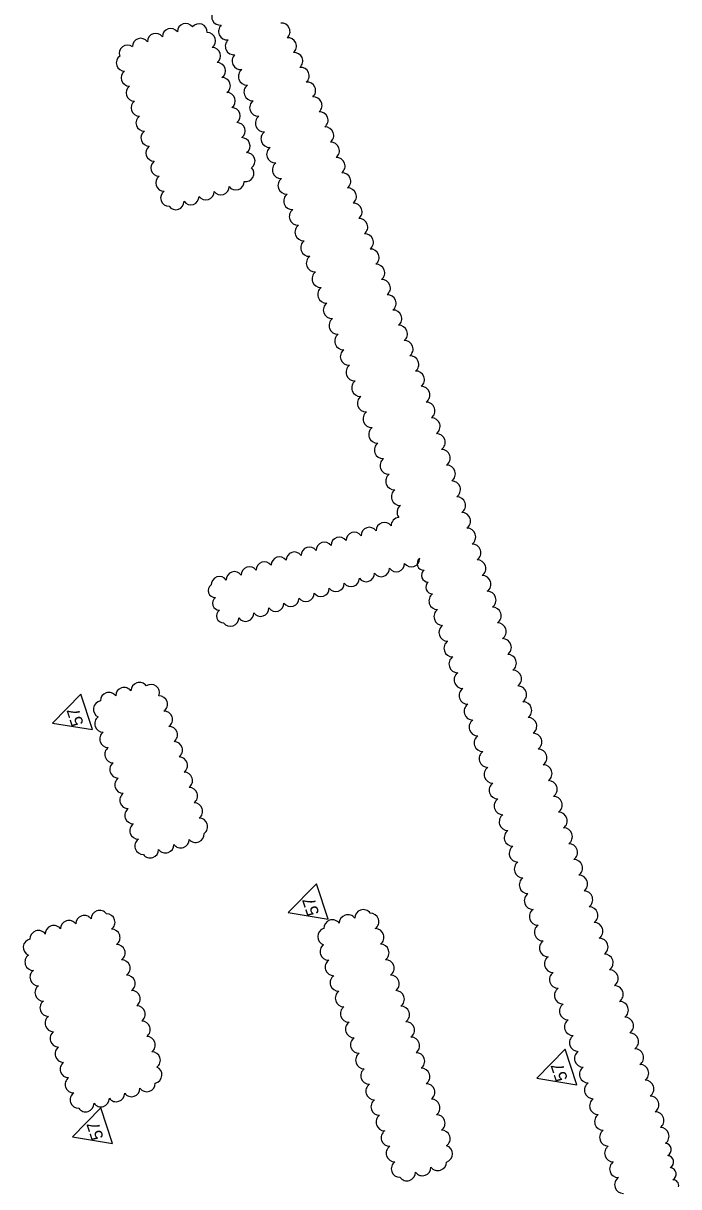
# Model space of a CAD drawing. Extents: x 929207 to 930387, y 631822 to 633132.
# Drawn here: x 929482 to 929778, y 632087 to 632613 of the extents above; entities that cross this region are included whole.
import ezdxf

# ---------------------------------------------------------------- set-up
doc = ezdxf.new("R2010")
doc.units = 0
doc.layers.add('PoleLight', color=7, linetype='Continuous')

msp = doc.modelspace()

# ---------------------------------------------------------------- linework, layer by layer
at = {"layer": 'PoleLight'}
for points in [[(929494.95, 632296.63), (929513.05, 632293.68), (929507.78, 632309.74)], [(929601.64, 632210.81), (929619.74, 632207.86), (929614.46, 632223.92)], [(929714.17, 632135.84), (929732.27, 632132.89), (929726.99, 632148.95)], [(929503.96, 632109.27), (929522.06, 632106.32), (929516.78, 632122.38)]]:
    msp.add_lwpolyline(points, close=True, dxfattribs=at)
for centre, radius, start, end in [((929570.83, 632616.45), 3.87, 132.1575, 277.1575), ((929541.6, 632605.1), 3.75, 35.6866, 180.6866), ((929548.4, 632607.33), 3.75, 35.6866, 180.6866), ((929555.19, 632609.56), 3.75, 35.6866, 180.6866), ((929561.18, 632609.43), 3.75, 356.7237, 141.7237), ((929564.97, 632605.47), 3.75, 305.6866, 90.6866), ((929573.92, 632609.74), 3.87, 132.1575, 277.1575), ((929598.62, 632609.71), 3.82, 310.9237, 95.9237), ((929528.86, 632599.78), 3.75, 54.2081, 199.2081), ((929534.8, 632602.87), 3.75, 35.6866, 180.6866), ((929577, 632603.02), 3.87, 132.1575, 277.1575), ((929601.52, 632603.02), 3.82, 310.9237, 95.9237), ((929527.51, 632595.5), 3.75, 125.6866, 270.6866), ((929567.2, 632598.67), 3.75, 305.6866, 90.6866), ((929580.08, 632596.31), 3.87, 132.1575, 277.1575), ((929604.41, 632596.33), 3.82, 310.9237, 95.9237), ((929569.44, 632591.87), 3.75, 305.6866, 90.6866), ((929607.31, 632589.64), 3.82, 310.9237, 95.9237), ((929529.74, 632588.71), 3.75, 125.6866, 270.6866), ((929571.67, 632585.08), 3.75, 305.6866, 90.6866), ((929582.96, 632589.35), 3.93, 127.5144, 272.5144), ((929531.98, 632581.91), 3.75, 125.6866, 270.6866), ((929585.52, 632582.3), 3.93, 127.5144, 272.5144), ((929610.21, 632582.95), 3.82, 310.9237, 95.9237), ((929534.21, 632575.11), 3.75, 125.6866, 270.6866), ((929573.9, 632578.28), 3.75, 305.6866, 90.6866), ((929588.09, 632575.26), 3.93, 127.5144, 272.5144), ((929613.11, 632576.26), 3.82, 310.9237, 95.9237), ((929576.13, 632571.48), 3.75, 305.6866, 90.6866), ((929615.81, 632569.51), 3.86, 307.897, 92.897), ((929536.44, 632568.32), 3.75, 125.6866, 270.6866), ((929578.37, 632564.69), 3.75, 305.6866, 90.6866), ((929590.66, 632568.21), 3.93, 127.5144, 272.5144), ((929618.38, 632562.61), 3.86, 307.897, 92.897), ((929538.67, 632561.52), 3.75, 125.6866, 270.6866), ((929580.6, 632557.89), 3.75, 305.6866, 90.6866), ((929593.22, 632561.16), 3.93, 127.5144, 272.5144), ((929540.91, 632554.72), 3.75, 125.6866, 270.6866), ((929595.79, 632554.12), 3.93, 127.5144, 272.5144), ((929620.95, 632555.7), 3.86, 307.897, 92.897), ((929543.14, 632547.93), 3.75, 125.6866, 270.6866), ((929582.83, 632551.09), 3.75, 305.6866, 90.6866), ((929623.51, 632548.8), 3.86, 307.897, 92.897), ((929582.33, 632545.43), 3.75, 259.2222, 44.2222), ((929598.36, 632547.07), 3.93, 127.5144, 272.5144), ((929626.08, 632541.89), 3.86, 307.897, 92.897), ((929545.37, 632541.13), 3.75, 125.6866, 270.6866), ((929577.88, 632541.7), 3.75, 215.6866, 0.6866), ((929600.92, 632540.03), 3.93, 127.5144, 272.5144), ((929547.61, 632534.33), 3.75, 125.6866, 270.6866), ((929557.49, 632535.01), 3.75, 215.6866, 0.6866), ((929564.29, 632537.24), 3.75, 215.6866, 0.6866), ((929571.09, 632539.47), 3.75, 215.6866, 0.6866), ((929603.49, 632532.98), 3.93, 127.5144, 272.5144), ((929628.65, 632534.99), 3.86, 307.897, 92.897), ((929550.7, 632532.77), 3.75, 215.6866, 0.6866), ((929631.22, 632528.08), 3.86, 307.897, 92.897), ((929606.05, 632525.94), 3.93, 127.5144, 272.5144), ((929633.78, 632521.18), 3.86, 307.897, 92.897), ((929608.62, 632518.89), 3.93, 127.5144, 272.5144), ((929611.19, 632511.84), 3.93, 127.5144, 272.5144), ((929636.35, 632514.27), 3.86, 307.897, 92.897), ((929638.92, 632507.37), 3.86, 307.897, 92.897), ((929613.75, 632504.8), 3.93, 127.5144, 272.5144), ((929641.49, 632500.46), 3.86, 307.897, 92.897), ((929616.32, 632497.75), 3.93, 127.5144, 272.5144), ((929618.89, 632490.71), 3.93, 127.5144, 272.5144), ((929644.05, 632493.56), 3.86, 307.897, 92.897), ((929646.62, 632486.65), 3.86, 307.897, 92.897), ((929621.45, 632483.66), 3.93, 127.5144, 272.5144), ((929649.19, 632479.75), 3.86, 307.897, 92.897), ((929624.02, 632476.61), 3.93, 127.5144, 272.5144), ((929626.59, 632469.57), 3.93, 127.5144, 272.5144), ((929651.76, 632472.84), 3.86, 307.897, 92.897), ((929654.32, 632465.94), 3.86, 307.897, 92.897), ((929629.15, 632462.52), 3.93, 127.5144, 272.5144), ((929656.89, 632459.03), 3.86, 307.897, 92.897), ((929631.72, 632455.48), 3.93, 127.5144, 272.5144), ((929659.46, 632452.13), 3.86, 307.897, 92.897), ((929634.29, 632448.43), 3.93, 127.5144, 272.5144), ((929661.86, 632445.14), 3.93, 305.3886, 90.3886), ((929636.85, 632441.39), 3.93, 127.5144, 272.5144), ((929664.16, 632438.01), 3.93, 305.3886, 90.3886), ((929639.42, 632434.34), 3.93, 127.5144, 272.5144), ((929666.47, 632430.87), 3.93, 305.3886, 90.3886), ((929641.99, 632427.29), 3.93, 127.5144, 272.5144), ((929668.77, 632423.73), 3.93, 305.3886, 90.3886), ((929644.55, 632420.25), 3.93, 127.5144, 272.5144), ((929671.08, 632416.59), 3.93, 305.3886, 90.3886), ((929647.12, 632413.2), 3.93, 127.5144, 272.5144), ((929649.68, 632406.16), 3.93, 127.5144, 272.5144), ((929673.38, 632409.45), 3.93, 305.3886, 90.3886), ((929675.68, 632402.31), 3.93, 305.3886, 90.3886), ((929652.25, 632399.11), 3.93, 127.5144, 272.5144), ((929677.99, 632395.17), 3.93, 305.3886, 90.3886), ((929654.82, 632392.07), 3.93, 127.5144, 217.1821), ((929645.16, 632383.72), 3.75, 35.6866, 180.6866), ((929651.95, 632385.95), 3.75, 94.0099, 180.6866), ((929680.29, 632388.03), 3.93, 305.3886, 90.3886), ((929631.58, 632379.26), 3.75, 35.6866, 180.6866), ((929638.37, 632381.49), 3.75, 35.6866, 180.6866), ((929682.6, 632380.89), 3.93, 305.3886, 90.3886), ((929618.01, 632374.8), 3.75, 35.6866, 180.6866), ((929624.79, 632377.03), 3.75, 35.6866, 180.6866), ((929684.9, 632373.75), 3.93, 305.3886, 90.3886), ((929597.64, 632368.11), 3.75, 35.6866, 180.6866), ((929604.43, 632370.34), 3.75, 35.6866, 180.6866), ((929611.22, 632372.57), 3.75, 35.6866, 180.6866), ((929584.06, 632363.65), 3.75, 35.6866, 180.6866), ((929590.85, 632365.88), 3.75, 35.6866, 180.6866), ((929643.74, 632366.64), 3.77, 215.6866, 0.6866), ((929650.57, 632368.88), 3.77, 215.6866, 0.6866), ((929657.4, 632371.12), 3.77, 215.6866, 0.6866), ((929662.99, 632368.8), 2.98, 127.5144, 272.5144), ((929687.21, 632366.61), 3.93, 305.3886, 90.3886), ((929570.49, 632359.19), 3.75, 35.6866, 180.6866), ((929577.27, 632361.42), 3.75, 35.6866, 180.6866), ((929630.08, 632362.15), 3.77, 215.6866, 0.6866), ((929636.91, 632364.39), 3.77, 215.6866, 0.6866), ((929664.93, 632363.46), 2.98, 127.5144, 272.5144), ((929689.51, 632359.47), 3.93, 305.3886, 90.3886), ((929568.58, 632356.58), 3.15, 125.6866, 270.6866), ((929616.42, 632357.66), 3.77, 215.6866, 0.6866), ((929623.25, 632359.9), 3.77, 215.6866, 0.6866), ((929666.88, 632358.12), 2.98, 127.5144, 272.5144), ((929691.81, 632352.33), 3.93, 305.3886, 90.3886), ((929570.46, 632350.87), 3.15, 125.6866, 270.6866), ((929595.93, 632350.93), 3.77, 215.6866, 0.6866), ((929602.76, 632353.17), 3.77, 215.6866, 0.6866), ((929609.59, 632355.42), 3.77, 215.6866, 0.6866), ((929669.27, 632351.93), 3.93, 125.154, 270.154), ((929572.34, 632345.15), 3.15, 125.6866, 270.6866), ((929582.27, 632346.44), 3.77, 215.6866, 0.6866), ((929589.1, 632348.68), 3.77, 215.6866, 0.6866), ((929671.54, 632344.79), 3.93, 125.154, 270.154), ((929694.12, 632345.19), 3.93, 305.3886, 90.3886), ((929575.44, 632344.2), 3.77, 215.6866, 0.6866), ((929673.82, 632337.65), 3.93, 125.154, 270.154), ((929696.42, 632338.05), 3.93, 305.3886, 90.3886), ((929698.73, 632330.91), 3.93, 305.3886, 90.3886), ((929676.09, 632330.5), 3.93, 125.154, 270.154), ((929678.36, 632323.36), 3.93, 125.154, 270.154), ((929701.03, 632323.77), 3.93, 305.3886, 90.3886), ((929680.64, 632316.22), 3.93, 125.154, 270.154), ((929703.34, 632316.64), 3.93, 305.3886, 90.3886), ((929534.23, 632311.21), 3.82, 35.6866, 180.6866), ((929539.5, 632310.29), 3.82, 339.6034, 124.6034), ((929520.4, 632306.67), 3.82, 35.6866, 180.6866), ((929527.32, 632308.94), 3.82, 35.6866, 180.6866), ((929543.13, 632305.14), 3.82, 305.6866, 90.6866), ((929682.91, 632309.07), 3.93, 125.154, 270.154), ((929705.64, 632309.5), 3.93, 305.3886, 90.3886), ((929517.21, 632302.86), 3.81, 99.5768, 244.5768), ((929685.18, 632301.93), 3.93, 125.154, 270.154), ((929707.95, 632302.36), 3.93, 305.3886, 90.3886), ((929517.8, 632296.31), 3.82, 125.6866, 270.6866), ((929545.4, 632298.23), 3.82, 305.6866, 90.6866), ((929687.46, 632294.79), 3.93, 125.154, 270.154), ((929710.25, 632295.22), 3.93, 305.3886, 90.3886), ((929520.08, 632289.39), 3.82, 125.6866, 270.6866), ((929547.67, 632291.31), 3.82, 305.6866, 90.6866), ((929549.95, 632284.39), 3.82, 305.6866, 90.6866), ((929689.73, 632287.64), 3.93, 125.154, 270.154), ((929712.55, 632288.08), 3.93, 305.3886, 90.3886), ((929522.35, 632282.48), 3.82, 125.6866, 270.6866), ((929692, 632280.5), 3.93, 125.154, 270.154), ((929714.86, 632280.94), 3.93, 305.3886, 90.3886), ((929524.62, 632275.56), 3.82, 125.6866, 270.6866), ((929552.22, 632277.47), 3.82, 305.6866, 90.6866), ((929717.16, 632273.8), 3.93, 305.3886, 90.3886), ((929526.89, 632268.64), 3.82, 125.6866, 270.6866), ((929554.49, 632270.55), 3.82, 305.6866, 90.6866), ((929694.28, 632273.36), 3.93, 125.154, 270.154), ((929556.76, 632263.64), 3.82, 305.6866, 90.6866), ((929696.55, 632266.21), 3.93, 125.154, 270.154), ((929719.47, 632266.66), 3.93, 305.3886, 90.3886), ((929529.17, 632261.72), 3.82, 125.6866, 270.6866), ((929698.82, 632259.07), 3.93, 125.154, 270.154), ((929721.77, 632259.52), 3.93, 305.3886, 90.3886), ((929531.44, 632254.8), 3.82, 125.6866, 270.6866), ((929559.04, 632256.72), 3.82, 305.6866, 90.6866), ((929724.08, 632252.38), 3.93, 305.3886, 90.3886), ((929533.71, 632247.89), 3.82, 125.6866, 270.6866), ((929561.31, 632249.8), 3.82, 305.6866, 90.6866), ((929701.1, 632251.93), 3.93, 125.154, 270.154), ((929559.73, 632246.4), 3.82, 219.4956, 4.4956), ((929703.37, 632244.79), 3.93, 125.154, 270.154), ((929726.38, 632245.24), 3.93, 305.3886, 90.3886), ((929535.99, 632240.97), 3.82, 125.6866, 270.6866), ((929546.05, 632241.65), 3.82, 215.6866, 0.6866), ((929552.97, 632243.92), 3.82, 215.6866, 0.6866), ((929705.64, 632237.64), 3.93, 125.154, 270.154), ((929728.69, 632238.1), 3.93, 305.3886, 90.3886), ((929539.13, 632239.38), 3.82, 215.6866, 0.6866), ((929730.99, 632230.96), 3.93, 305.3886, 90.3886), ((929707.92, 632230.5), 3.93, 125.154, 270.154), ((929710.19, 632223.36), 3.93, 125.154, 270.154), ((929733.29, 632223.82), 3.93, 305.3886, 90.3886), ((929712.46, 632216.21), 3.93, 125.154, 270.154), ((929735.6, 632216.68), 3.93, 305.3886, 90.3886), ((929737.9, 632209.54), 3.93, 305.3886, 90.3886), ((929509.29, 632205.73), 3.83, 35.6866, 180.6866), ((929516.22, 632208.01), 3.83, 35.6866, 180.6866), ((929519.38, 632206.42), 3.83, 305.6866, 90.6866), ((929628.6, 632206.02), 3.87, 35.6866, 180.6866), ((929635.62, 632208.32), 3.87, 35.6866, 180.6866), ((929638.81, 632206.71), 3.87, 305.6866, 90.6866), ((929714.74, 632209.07), 3.93, 125.154, 270.154), ((929495.42, 632201.17), 3.83, 35.6866, 180.6866), ((929502.35, 632203.45), 3.83, 35.6866, 180.6866), ((929521.66, 632199.48), 3.83, 305.6866, 90.6866), ((929618.84, 632199.96), 3.87, 106.858, 251.858), ((929621.59, 632203.71), 3.87, 35.6866, 180.6866), ((929641.12, 632199.69), 3.87, 305.6866, 90.6866), ((929717.01, 632201.93), 3.93, 125.154, 270.154), ((929740.21, 632202.4), 3.93, 305.3886, 90.3886), ((929485.46, 632195.11), 3.82, 102.1164, 247.1164), ((929488.48, 632198.9), 3.83, 35.6866, 180.6866), ((929719.28, 632194.78), 3.93, 125.154, 270.154), ((929742.51, 632195.27), 3.93, 305.3886, 90.3886), ((929523.93, 632192.55), 3.83, 305.6866, 90.6866), ((929619.89, 632193.13), 3.87, 125.6866, 270.6866), ((929643.43, 632192.67), 3.87, 305.6866, 90.6866), ((929486.21, 632188.48), 3.83, 125.6866, 270.6866), ((929526.21, 632185.61), 3.83, 305.6866, 90.6866), ((929622.2, 632186.12), 3.87, 125.6866, 270.6866), ((929645.73, 632185.65), 3.87, 305.6866, 90.6866), ((929721.56, 632187.64), 3.93, 125.154, 270.154), ((929744.82, 632188.13), 3.93, 305.3886, 90.3886), ((929488.48, 632181.55), 3.83, 125.6866, 270.6866), ((929528.49, 632178.68), 3.83, 305.6866, 90.6866), ((929624.5, 632179.1), 3.87, 125.6866, 270.6866), ((929648.04, 632178.64), 3.87, 305.6866, 90.6866), ((929723.83, 632180.5), 3.93, 125.154, 270.154), ((929747.12, 632180.99), 3.93, 305.3886, 90.3886), ((929490.76, 632174.61), 3.83, 125.6866, 270.6866), ((929726.1, 632173.35), 3.93, 125.154, 270.154), ((929749.42, 632173.85), 3.93, 305.3886, 90.3886), ((929530.77, 632171.74), 3.83, 305.6866, 90.6866), ((929626.81, 632172.08), 3.87, 125.6866, 270.6866), ((929650.34, 632171.62), 3.87, 305.6866, 90.6866), ((929493.04, 632167.68), 3.83, 125.6866, 270.6866), ((929533.05, 632164.81), 3.83, 305.6866, 90.6866), ((929629.11, 632165.06), 3.87, 125.6866, 270.6866), ((929652.65, 632164.6), 3.87, 305.6866, 90.6866), ((929728.38, 632166.21), 3.93, 125.154, 270.154), ((929751.73, 632166.71), 3.93, 305.3886, 90.3886), ((929495.32, 632160.74), 3.83, 125.6866, 270.6866), ((929535.32, 632157.87), 3.83, 305.6866, 90.6866), ((929631.42, 632158.04), 3.87, 125.6866, 270.6866), ((929654.95, 632157.58), 3.87, 305.6866, 90.6866), ((929730.65, 632159.07), 3.93, 125.154, 270.154), ((929754.03, 632159.57), 3.93, 305.3886, 90.3886), ((929497.6, 632153.81), 3.83, 125.6866, 270.6866), ((929756.34, 632152.43), 3.93, 305.3886, 90.3886), ((929537.6, 632150.94), 3.83, 305.6866, 90.6866), ((929633.72, 632151.02), 3.87, 125.6866, 270.6866), ((929657.26, 632150.56), 3.87, 305.6866, 90.6866), ((929732.92, 632151.92), 3.93, 125.154, 270.154), ((929499.87, 632146.87), 3.83, 125.6866, 270.6866), ((929539.88, 632144), 3.83, 305.6866, 90.6866), ((929636.03, 632144.01), 3.87, 125.6866, 270.6866), ((929659.57, 632143.54), 3.87, 305.6866, 90.6866), ((929735.2, 632144.78), 3.93, 125.154, 270.154), ((929758.64, 632145.29), 3.93, 305.3886, 90.3886), ((929502.15, 632139.94), 3.83, 125.6866, 270.6866), ((929540.63, 632137.37), 3.82, 282.1164, 67.1164), ((929638.33, 632136.99), 3.87, 125.6866, 270.6866), ((929661.87, 632136.53), 3.87, 305.6866, 90.6866), ((929737.47, 632137.64), 3.93, 125.154, 270.154), ((929760.95, 632138.15), 3.93, 305.3886, 90.3886), ((929504.43, 632133), 3.83, 125.6866, 270.6866), ((929763.25, 632131.01), 3.93, 305.3886, 90.3886), ((929506.71, 632126.07), 3.83, 125.6866, 270.6866), ((929530.67, 632131.31), 3.83, 215.6866, 0.6866), ((929537.6, 632133.59), 3.83, 215.6866, 0.6866), ((929640.64, 632129.97), 3.87, 125.6866, 270.6866), ((929664.18, 632129.51), 3.87, 305.6866, 90.6866), ((929739.74, 632130.49), 3.93, 125.154, 270.154), ((929509.86, 632124.48), 3.83, 215.6866, 0.6866), ((929516.8, 632126.75), 3.83, 215.6866, 0.6866), ((929523.73, 632129.03), 3.83, 215.6866, 0.6866), ((929642.95, 632122.95), 3.87, 125.6866, 270.6866), ((929666.48, 632122.49), 3.87, 305.6866, 90.6866), ((929742.02, 632123.35), 3.93, 125.154, 270.154), ((929765.56, 632123.87), 3.93, 305.3886, 90.3886), ((929645.25, 632115.93), 3.87, 125.6866, 270.6866), ((929668.79, 632115.47), 3.87, 305.6866, 90.6866), ((929744.29, 632116.21), 3.93, 125.154, 270.154), ((929767.86, 632116.73), 3.93, 305.3886, 90.3886), ((929770.16, 632109.59), 3.93, 305.3886, 90.3886), ((929647.56, 632108.92), 3.87, 125.6866, 270.6866), ((929671.09, 632108.45), 3.87, 305.6866, 90.6866), ((929746.56, 632109.07), 3.93, 125.154, 270.154), ((929649.86, 632101.9), 3.87, 125.6866, 270.6866), ((929672.15, 632101.63), 3.87, 286.858, 71.858), ((929748.84, 632101.92), 3.93, 125.154, 270.154), ((929772.13, 632103.46), 2.94, 298.9028, 83.9028), ((929652.17, 632094.88), 3.87, 125.6866, 270.6866), ((929669.4, 632097.88), 3.87, 215.6866, 0.6866), ((929751.11, 632094.78), 3.93, 125.154, 270.154), ((929773.24, 632097.96), 2.94, 298.9028, 83.9028), ((929655.36, 632093.27), 3.87, 215.6866, 0.6866), ((929662.38, 632095.57), 3.87, 215.6866, 0.6866), ((929774.35, 632092.45), 2.94, 298.9028, 83.9028), ((929753.38, 632087.64), 3.93, 125.154, 270.154), ((929775.8, 632087.21), 2.66, 349.8687, 90.6866)]:
    msp.add_arc(centre, radius, start, end, dxfattribs=at)

# ---------------------------------------------------------------- texts
for p in [(929509.06, 632296.29), (929615.75, 632210.47), (929728.28, 632135.5), (929518.07, 632108.93)]:
    msp.add_text('57', height=5.6, rotation=108.1866, dxfattribs=at).set_placement(p)

doc.saveas('drawing.dxf')
